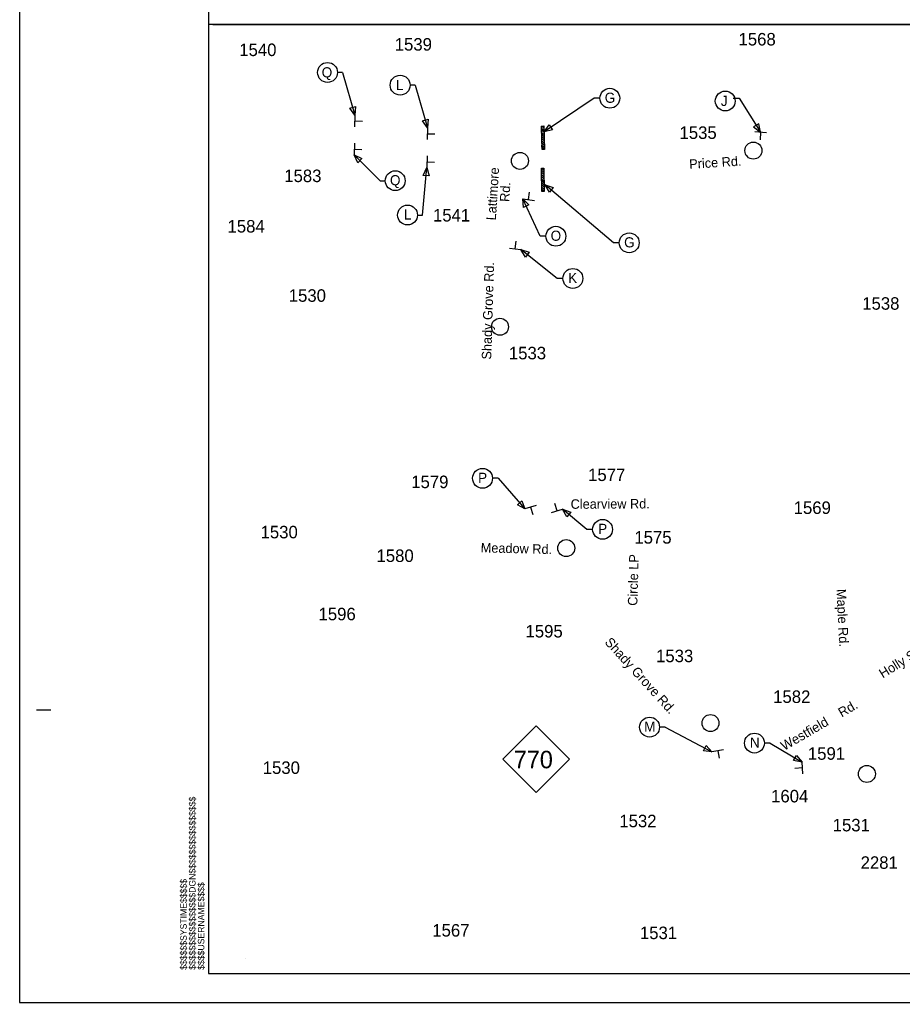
# Model space of a CAD drawing. Extents: x 2157572 to 5059327, y 715220 to 1674494.
# Drawn here: x 2157572 to 2163670, y 722289 to 729076 of the extents above; entities that cross this region are included whole.
import ezdxf

# ---------------------------------------------------------------- set-up
doc = ezdxf.new("R2010")
doc.units = 0
for name, color, linetype in [('Exist Cultural Church Label', 7, 'Continuous'), ('Exist Cultural Recreational Athletic Track', 7, 'Continuous'), ('Exist Map Preparation Border Sheet 1 CELL', 7, 'Continuous'), ('Exist Road Primary US Shield CELL', 7, 'Continuous'), ('Exist Road Primary US Structure Standard Bridge Number Label', 7, 'Continuous'), ('Exist Road Secondary Type 41 SR Number Label', 7, 'Continuous'), ('Exist Road Secondary Type 51 Divided Label', 7, 'Continuous'), ('Exist Road Secondary Type 51 Undivided 3 Lane Attributed', 7, 'Continuous'), ('Level 51', 7, 'Continuous'), ('Level 53', 7, 'Continuous'), ('Map Preparation County Base Legend Highway Garage or Maintenance Office', 7, 'Continuous'), ('Map Preparation County Base Legend Monument Small Historical Site', 7, 'Continuous'), ('Map Preparation County Base Legend Weight Station', 7, 'Continuous'), ('Map Preparation County North Arrow Shadow', 7, 'Continuous'), ('Map Preparation County North Arrow White Shapes', 7, 'Continuous')]:
    doc.layers.add(name, color=color, linetype=linetype)

msp = doc.modelspace()

# ---------------------------------------------------------------- linework, layer by layer
at = {"layer": 'Exist Cultural Church Label'}
for centre in [(2159698.8, 728711), (2160200.4, 728623.1), (2161649, 728532.8), (2162446.3, 728513.8), (2160166.5, 727963.3), (2160251.5, 727726.3), (2161276.1, 727579.8), (2161782.8, 727534.2), (2161393.6, 727288.2), (2160769.7, 725907.8), (2161598.9, 725555.2), (2161923.4, 724189.4), (2162648.1, 724079.2)]:
    msp.add_circle(centre, 68.6, dxfattribs=at)
at = {"layer": 'Exist Map Preparation Border Sheet 1 CELL'}
msp.add_line((2159130.3, 722592.1), (2159130.3, 722592.1), dxfattribs=at)
at = {"layer": 'Exist Road Secondary Type 41 SR Number Label'}
for p, q in [((2161176.9, 728340.9), (2161193.2, 728341.3)), ((2161193.5, 728325.3), (2161176.9, 728340.9)), ((2161177.2, 728340.9), (2161193.2, 728341.3)), ((2161180.8, 728179), (2161177.2, 728340.9)), ((2161177.3, 728326.3), (2161193.8, 728310.7)), ((2161177.6, 728311.8), (2161177.3, 728326.3)), ((2161193.2, 728341.3), (2161193.5, 728325.3)), ((2161193.2, 728341.3), (2161196.8, 728179.4)), ((2161194.2, 728296.2), (2161177.6, 728311.8)), ((2161177.9, 728297.2), (2161194.5, 728281.6)), ((2161178.2, 728282.6), (2161177.9, 728297.2)), ((2161194.8, 728267), (2161178.2, 728282.6)), ((2161178.6, 728268.1), (2161195.1, 728252.5)), ((2161178.9, 728253.5), (2161178.6, 728268.1)), ((2161195.5, 728237.9), (2161178.9, 728253.5)), ((2161193.8, 728310.7), (2161194.2, 728296.2)), ((2161194.5, 728281.6), (2161194.8, 728267)), ((2161195.1, 728252.5), (2161195.5, 728237.9)), ((2161179.2, 728238.9), (2161195.8, 728223.1)), ((2161179.6, 728224.4), (2161179.2, 728238.9)), ((2161196.1, 728208.5), (2161179.6, 728224.4)), ((2161179.9, 728209.8), (2161196.5, 728193.9)), ((2161180.2, 728195.2), (2161179.9, 728209.8)), ((2161196.8, 728179.4), (2161180.2, 728195.2)), ((2161196.8, 728179.4), (2161180.8, 728179)), ((2161195.8, 728223.1), (2161196.1, 728208.5)), ((2161196.5, 728193.9), (2161196.8, 728179.4)), ((2161175.8, 728050.1), (2161192, 728050.5)), ((2161192.4, 728034.5), (2161175.8, 728050.1)), ((2161176.1, 728050.1), (2161192, 728050.5)), ((2161179.7, 727888.2), (2161176.1, 728050.1)), ((2161192, 728050.5), (2161192.4, 728034.5)), ((2161192, 728050.5), (2161195.6, 727888.6)), ((2161176.1, 728035.5), (2161192.7, 728020)), ((2161176.5, 728021), (2161176.1, 728035.5)), ((2161193, 728005.4), (2161176.5, 728021)), ((2161176.8, 728006.4), (2161193.4, 727990.8)), ((2161177.1, 727991.9), (2161176.8, 728006.4)), ((2161193.7, 727976.3), (2161177.1, 727991.9)), ((2161177.4, 727977.3), (2161194, 727961.7)), ((2161177.8, 727962.7), (2161177.4, 727977.3)), ((2161192.7, 728020), (2161193, 728005.4)), ((2161193.4, 727990.8), (2161193.7, 727976.3)), ((2161194.3, 727947.1), (2161177.8, 727962.7)), ((2161178.1, 727948.2), (2161194.7, 727932.3)), ((2161178.4, 727933.6), (2161178.1, 727948.2)), ((2161195, 727917.7), (2161178.4, 727933.6)), ((2161178.7, 727919), (2161195.3, 727903.2)), ((2161179.1, 727904.5), (2161178.7, 727919)), ((2161194, 727961.7), (2161194.3, 727947.1)), ((2161194.7, 727932.3), (2161195, 727917.7)), ((2161195.6, 727888.6), (2161179.1, 727904.5)), ((2161195.6, 727888.6), (2161179.7, 727888.2)), ((2161195.3, 727903.2), (2161195.6, 727888.6))]:
    msp.add_line(p, q, dxfattribs=at)
at = {"layer": 'Exist Road Secondary Type 51 Divided Label'}
msp.add_lwpolyline([(2157571.9, 722288.7), (2171075.9, 722288.7), (2171075.9, 731088.6), (2157571.9, 731088.6)], close=True, dxfattribs=at)
at = {"layer": 'Exist Road Secondary Type 51 Undivided 3 Lane Attributed'}
msp.add_lwpolyline([(2170485.5, 727897.1), (2170495.8, 729042.7), (2158875.9, 729042.7), (2158875.9, 722488.7), (2166434.4, 722488.7), (2166434.4, 723622.8), (2170875.9, 723622.8), (2170875.9, 727897.1)], close=True, dxfattribs=at)
at = {"layer": 'Level 51'}
for p, q in [((2159803.1, 728711), (2159767.4, 728711)), ((2159803.1, 728711), (2159888.5, 728417)), ((2160304.7, 728623.1), (2160269, 728623.1)), ((2160304.7, 728623.1), (2160390.1, 728329)), ((2161540.7, 728532.8), (2161194.3, 728300.7)), ((2161580.4, 728532.8), (2161540.7, 728532.8)), ((2162501.8, 728532.8), (2162541.4, 728532.8)), ((2162541.4, 728532.8), (2162690.1, 728298.3)), ((2160062.2, 727963.3), (2159882.4, 728141.9)), ((2160355.8, 727726.3), (2160384, 728053.9)), ((2160062.2, 727963.3), (2160097.9, 727963.3)), ((2161674.9, 727534.2), (2161202.1, 727935.8)), ((2161167.8, 727579.8), (2161047.3, 727838.2)), ((2160320.1, 727726.3), (2160355.8, 727726.3)), ((2161207.4, 727579.8), (2161167.8, 727579.8)), ((2161714.2, 727534.2), (2161674.6, 727534.2)), ((2161285.4, 727288.2), (2161035.2, 727487.4)), ((2161325, 727288.2), (2161285.4, 727288.2)), ((2160878, 725907.8), (2160838.4, 725907.8)), ((2160878, 725907.8), (2161062.8, 725696.4)), ((2161490.6, 725555.2), (2161322.9, 725694.5)), ((2161530.2, 725555.2), (2161490.6, 725555.2)), ((2162031.6, 724189.4), (2161992, 724189.4)), ((2162031.6, 724189.4), (2162354.6, 724018.9)), ((2162756.4, 724079.2), (2162716.8, 724079.2)), ((2162756.4, 724079.2), (2162977, 723947.7))]:
    msp.add_line(p, q, dxfattribs=at)
for points in [[(2159853, 728465), (2159892.8, 728476.6), (2159888.5, 728417)], [(2160354.6, 728377.1), (2160394.4, 728388.6), (2160390.1, 728329)], [(2161229.2, 728349), (2161252.5, 728314.7), (2161194.5, 728300.4)], [(2162677.6, 728356.7), (2162642.5, 728334.5), (2162690.1, 728298.3)], [(2159936.8, 728117.1), (2159907.5, 728087.7), (2159882.4, 728141.9)], [(2160399.8, 727996.3), (2160358.5, 727999.9), (2160384, 728053.9)], [(2161258.1, 727915.4), (2161231.5, 727883.6), (2161201.9, 727935.6)], [(2161090, 727796.4), (2161052.5, 727778.7), (2161047.3, 727838.2)], [(2161092, 727469), (2161066.4, 727436.4), (2161035.2, 727487.4)], [(2161010.3, 725724.9), (2161041.5, 725752.2), (2161062.8, 725696.4)], [(2161379.3, 725674.6), (2161352.8, 725642.8), (2161322.9, 725694.5)], [(2162295.3, 724026.7), (2162314.7, 724063.4), (2162354.6, 724018.9)], [(2162918.2, 723958.6), (2162939.5, 723994.2), (2162977, 723947.7)]]:
    msp.add_lwpolyline(points, close=True, dxfattribs=at)
for centre in [(2162640.4, 728171.1), (2161028.3, 728099.9), (2160890.2, 726954.8), (2161347.9, 725426), (2162344.4, 724217.8), (2163424.7, 723865.9)]:
    msp.add_circle(centre, 58.7, dxfattribs=at)
at = {"layer": 'Map Preparation County Base Legend Highway Garage or Maintenance Office'}
for centre in [(2159698.8, 728711), (2160200.4, 728623.1), (2161649, 728532.8), (2162446.3, 728513.8), (2160166.5, 727963.3), (2160251.5, 727726.3), (2161276.1, 727579.8), (2161782.8, 727534.2), (2161393.6, 727288.2), (2160769.7, 725907.8), (2161598.9, 725555.2), (2161923.4, 724189.4), (2162648.1, 724079.2)]:
    msp.add_circle(centre, 68.6, dxfattribs=at)
at = {"layer": 'Map Preparation County Base Legend Monument Small Historical Site'}
msp.add_lwpolyline([(2160910, 723967.2), (2161140.2, 724197.4), (2161370.4, 723967.2), (2161140.2, 723736.9)], close=True, dxfattribs=at)
at = {"layer": 'Map Preparation County North Arrow Shadow'}
for p, q in [((2159888.5, 728417), (2159885.3, 728336.1)), ((2159886.9, 728376.2), (2159939.3, 728374.1)), ((2160390.1, 728329), (2160386.9, 728248.1)), ((2160388.5, 728288.2), (2160440.9, 728286.2)), ((2162731.5, 728294.1), (2162650.7, 728300.9)), ((2162690.8, 728297.5), (2162686.4, 728245.2)), ((2159885.6, 728222.8), (2159882.4, 728141.9)), ((2159884, 728182), (2159936.4, 728180)), ((2160387.2, 728134.9), (2160384, 728053.9)), ((2160385.6, 728094.1), (2160438, 728092)), ((2161087.8, 727832.9), (2161094.7, 727884.9)), ((2161047.3, 727838.2), (2161127.6, 727827.6)), ((2160995.3, 727492.6), (2161002.2, 727544.7)), ((2160954.9, 727498), (2161035.2, 727487.4)), ((2161140.3, 725719.8), (2161062.8, 725696.4)), ((2161101.2, 725708), (2161116.4, 725657.8)), ((2161245.3, 725671.4), (2161322.9, 725694.5)), ((2161284.4, 725683.1), (2161269.4, 725733.4)), ((2162434.3, 724033), (2162354.6, 724018.9)), ((2162394.1, 724025.9), (2162403.3, 723974.2)), ((2162979.4, 723907.6), (2162927, 723904.4)), ((2162981.9, 723866.9), (2162977, 723947.7))]:
    msp.add_line(p, q, dxfattribs=at)
at = {"layer": 'Map Preparation County North Arrow White Shapes'}
for p, q in [((2158905.6, 729042.7), (2170875.9, 729042.7)), ((2157687.9, 724308.7), (2157787.9, 724308.7)), ((2158875.9, 722488.7), (2158875.9, 722488.7))]:
    msp.add_line(p, q, dxfattribs=at)
msp.add_lwpolyline([(2170875.9, 730888.7), (2158875.9, 730888.7), (2158875.9, 722488.7), (2170875.9, 722488.7)], close=True, dxfattribs=at)

# ---------------------------------------------------------------- texts
at = {"layer": 'Exist Cultural Church Label'}
for s, p in [('Q', (2159658.6, 728676.9)), ('L', (2160171, 728588.9))]:
    msp.add_text(s, height=70, dxfattribs=at).set_placement(p)
at = {"layer": 'Exist Cultural Recreational Athletic Track'}
msp.add_text('Holly St.', height=65.68, rotation=31.87305, dxfattribs=at).set_placement((2163534.5, 724524.5))
at = {"layer": 'Exist Road Primary US Shield CELL'}
for s, height, rotation, p in [('Price Rd.', 65.68, 3.63317, (2162199.4, 728044.6)), ('Lattimore', 65.68, 86.37448, (2160861.3, 727688.1)), (' Rd.', 65.68, 86.37448, (2160952.4, 727791)), ('Shady Grove Rd.', 65.681, 88.29271, (2160829.7, 726727.4)), ('Clearview Rd.', 65.681, 0.30274, (2161378.5, 725697.1)), ('Meadow Rd.', 65.68, 358.56732, (2160756.4, 725396.7)), ('Circle LP', 65.68, 88.38079, (2161838.7, 725026.8)), ('Maple Rd.', 65.68, 272.7549, (2163214.8, 725142.1)), ('Shady Grove Rd.', 65.681, 312.32823, (2161609.3, 724772.4)), ('Westfield    Rd.', 65.681, 30.16603, (2162854.1, 724024.9))]:
    msp.add_text(s, height=height, rotation=rotation, dxfattribs=at).set_placement(p)
at = {"layer": 'Exist Road Primary US Structure Standard Bridge Number Label'}
for s, p in [('G', (2161613.8, 728501.4)), ('J', (2162415.9, 728479.8)), ('Q', (2160130, 727931.9)), ('L', (2160225.8, 727694.9)), ('O', (2161240, 727548.4)), ('G', (2161747.6, 727502.8)), ('K', (2161360.9, 727256.7)), ('P', (2160739, 725876.4)), ('P', (2161568.1, 725523.8)), ('M', (2161886.1, 724158)), ('N', (2162616.6, 724047.8))]:
    msp.add_text(s, height=70, dxfattribs=at).set_placement(p)
at = {"layer": 'Level 53'}
for s, p in [('1539', (2160163.1, 728861.7)), ('1568', (2162538, 728897.3)), ('1540', (2159088.9, 728824.2)), ('1535', (2162130.3, 728252)), ('1583', (2159399.8, 727953.8)), ('1541', (2160427.2, 727681.6)), ('1584', (2159008, 727605.4)), ('1530', (2159430.9, 727127.1)), ('1538', (2163392.6, 727072.3)), ('1533', (2160951.6, 726729.6)), ('1577', (2161498.9, 725889.2)), ('1579', (2160277, 725840.1)), ('1569', (2162918.9, 725661.6)), ('1530', (2159236.3, 725493.3)), ('1575', (2161818.4, 725456.8)), ('1580', (2160037.2, 725330)), ('1596', (2159636.6, 724927.4)), ('1595', (2161066.5, 724808.5)), ('1533', (2161968.2, 724638.1)), ('1582', (2162777.3, 724356.3)), ('1591', (2163017.1, 723964)), ('1530', (2159251.2, 723866.2)), ('1604', (2162763, 723669.6)), ('1532', (2161714.5, 723497.9)), ('1531', (2163188.4, 723469.5)), ('2281', (2163381.5, 723210.8)), ('1567', (2160422.5, 722742.8)), ('1531', (2161856.7, 722725.4))]:
    msp.add_text(s, height=86.42, dxfattribs=at).set_placement(p)
at = {"layer": 'Map Preparation County Base Legend Weight Station'}
msp.add_text('770', height=120.99, dxfattribs=at).set_placement((2160985.4, 723905.1))
at = {"layer": 'Map Preparation County North Arrow White Shapes'}
for s, p in [('$$$$$$$$$$$$$$$$DGN$$$$$$$$$$$$$$$$', (2158787, 722513.3)), ('$$$$$$SYSTIME$$$$$', (2158726.3, 722513.3)), ('$$$$USERNAME$$$$', (2158847.6, 722513.3))]:
    msp.add_text(s, height=44.672, rotation=90, dxfattribs=at).set_placement(p)

doc.saveas('drawing.dxf')
